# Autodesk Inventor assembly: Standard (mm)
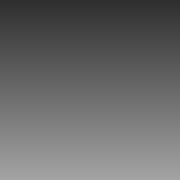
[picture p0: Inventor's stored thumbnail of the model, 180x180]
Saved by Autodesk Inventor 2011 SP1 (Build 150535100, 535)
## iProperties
Shininess: 64.0
Length Units: 11269
Angle Units: 11279
Time Units: 11290
Mass Units: 11283
Length Display Precision: 3
Angle Display Precision: 2
Compacted: True
Created: 2002-07
Part Number: Standard (mm)
Document SubType Name: Assembly
Density: 0.0
Volumn: 0.0
Area: 0.0
PropertySet Name: Model Information
Control State: 0
Master: False
Checked Out: False
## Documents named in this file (1)
- M:\Programs\AUT_Inventor2011EN\Templates\Standard.iam
